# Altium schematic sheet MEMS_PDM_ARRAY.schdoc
size 191 x 135 mm
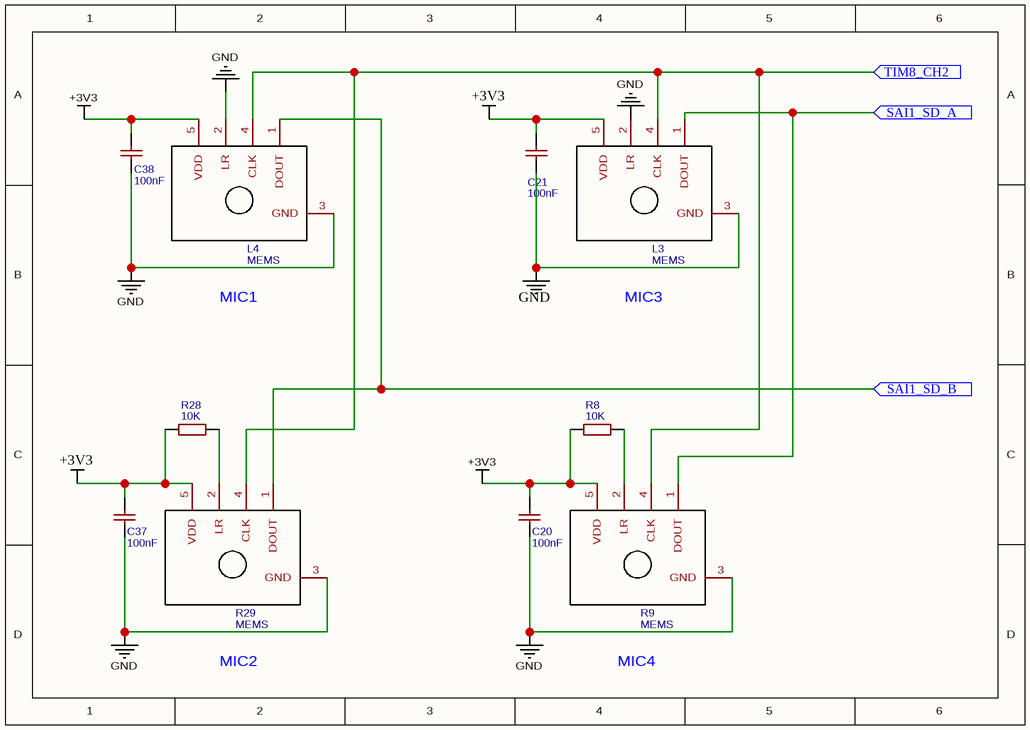
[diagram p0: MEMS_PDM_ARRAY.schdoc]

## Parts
C20  100nF  [C0805]
C21  100nF  [C0805]
C37  100nF  [C0805]
C38  100nF  [C0805]
L3  MEMS  [SPH0641LU4H-1]
L4  MEMS  [SPH0641LU4H-1]
R8  10K  [R0805]
R9  MEMS  [SPH0641LU4H-1]
R28  10K  [R0805]
R29  MEMS  [SPH0641LU4H-1]

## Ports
SAI1_SD_A (in), SAI1_SD_B (in), TIM8_CH2 (in)

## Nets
+3V3: C20.1 C21.1 C37.1 C38.1 L3.5(VDD) L4.5(VDD) R8.1 R9.5(VDD) R28.1 R29.5(VDD)
GND: C20.2 C21.2 C37.2 C38.2 L3.2(LR) L3.3(GND) L4.2(LR) L4.3(GND) R9.3(GND) R29.3(GND)
SAI1_SD_A: L3.1(DOUT) R9.1(DOUT) ; port SAI1_SD_A
SAI1_SD_B: L4.1(DOUT) R29.1(DOUT) ; port SAI1_SD_B
TIM8_CH2: L3.4(CLK) L4.4(CLK) R9.4(CLK) R29.4(CLK) ; port TIM8_CH2
NetR8_2: R8.2 R9.2(LR)
NetR28_2: R28.2 R29.2(LR)

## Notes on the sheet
- +3V3
- MIC1
- GND
- MIC3
- MIC2
- MIC4

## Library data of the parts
C20 C21 C37 C38 = 100nF: BOM_Manufacturer: YAGEO; BOM_Manufacturer Part: CC0805JRX7R9BB104; nameAlias: Capacitance
L3 L4 R9 R29 = MEMS: Contributor: WZS_123
R8 R28 = 10K: BOM_Manufacturer: FH; BOM_Manufacturer Part: RS-05K1002FT; nameAlias: Resistance (Ohms)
